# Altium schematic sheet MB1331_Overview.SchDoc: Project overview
size A4; Date: Not used; ApprovedBy: Not used; CheckedBy: Not used; Author: Not used; CompanyName: STMicroelectronics; DrawnBy: Not used; Engineer: Not used; Organization: Not used; Address1: Not used; Address2: Not used; Address3: Not used; Address4: Not used; DocumentNumber: Not used; Revision: Not used; SheetNumber: 1; SheetTotal: 23
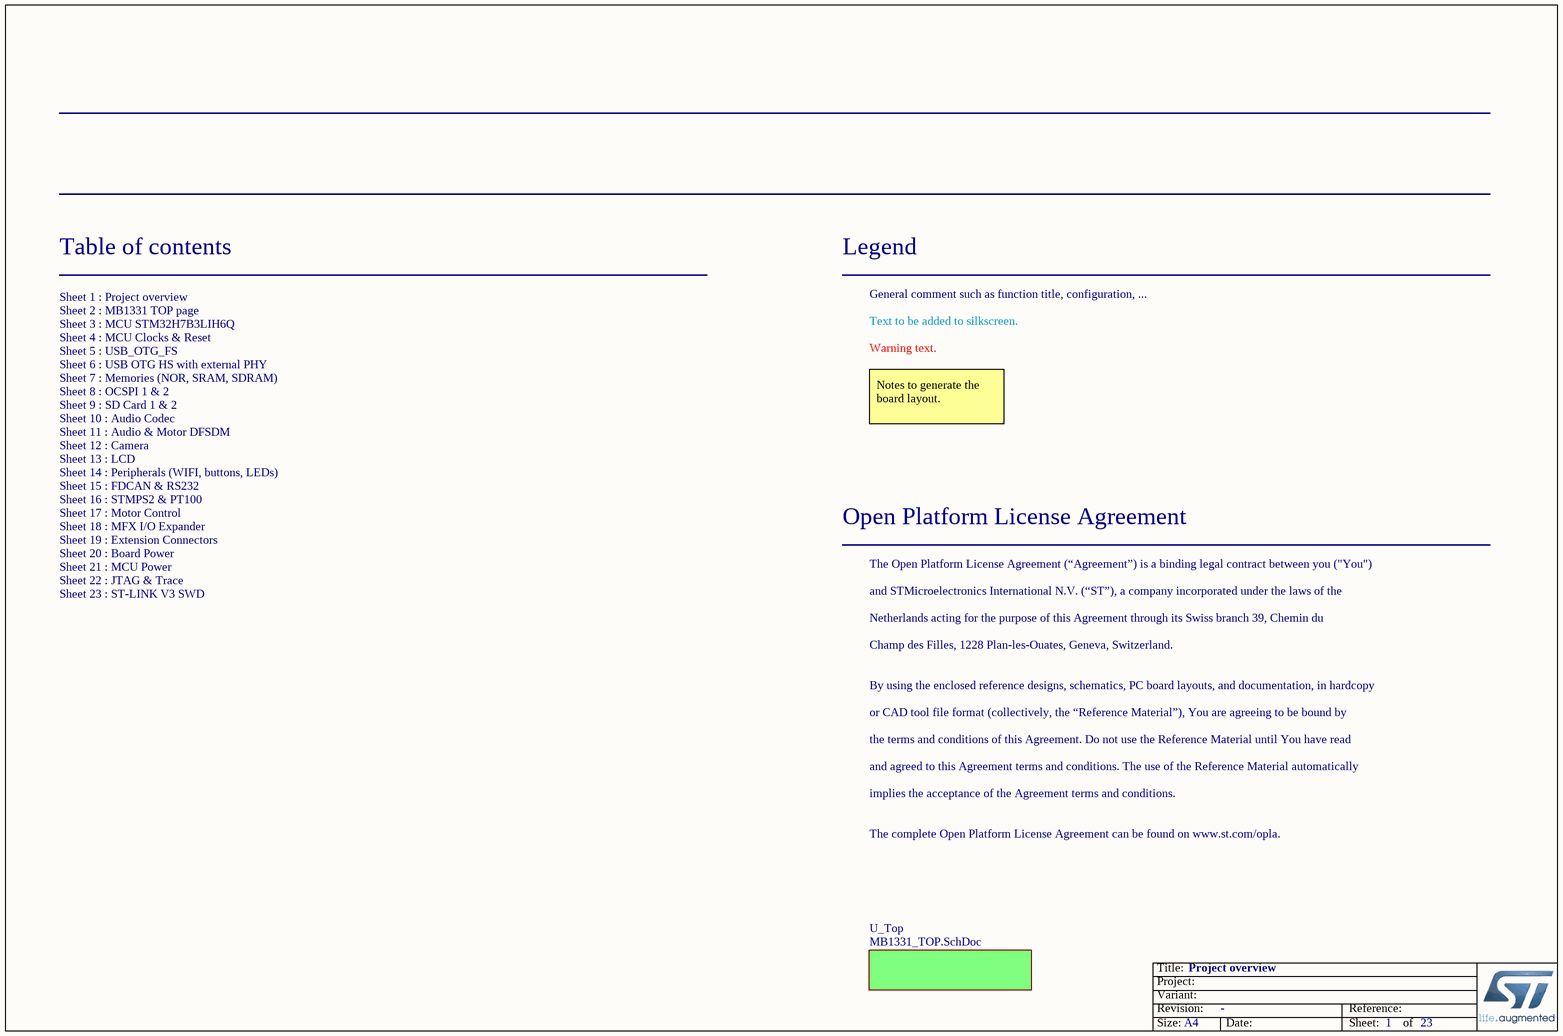
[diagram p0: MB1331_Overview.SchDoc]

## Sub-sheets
U_Top = MB1331_TOP.SchDoc: no entries

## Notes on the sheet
- Table of contents
- Legend
- General comment such as function title, configuration, ...
- Text to be added to silkscreen.
- Warning text.
- Notes to generate the board layout.
- Open Platform License Agreement
- The Open Platform License Agreement (“Agreement”) is a binding legal contract between you ("You")
- Sheet 1 : Project overview
  Sheet 2 : MB1331 TOP page
  Sheet 3 : MCU STM32H7B3LIH6Q
  Sheet 4 : MCU Clocks & Reset
  Sheet 5 : USB_OTG_FS
  Sheet 6 : USB OTG HS with external PHY
  Sheet 7 : Memories (NOR, SRAM, SDRAM)
  Sheet 8 : OCSPI 1 & 2
  Sheet 9 : SD Card 1 & 2
  Sheet 10 : Audio Codec
  Sheet 11 : Audio & Motor DFSDM
  Sheet 12 : Camera
  Sheet 13 : LCD
  Sheet 14 : Peripherals (WIFI, buttons, LEDs)
  Sheet 15 : FDCAN & RS232
  Sheet 16 : STMPS2 & PT100
  Sheet 17 : Motor Control
  Sheet 18 : MFX I/O Expander
  Sheet 19 : Extension Connectors
  Sheet 20 : Board Power
  Sheet 21 : MCU Power
  Sheet 22 : JTAG & Trace
  Sheet 23 : ST-LINK V3 SWD
- and STMicroelectronics International N.V. (“ST”), a company incorporated under the laws of the
- Netherlands acting for the purpose of this Agreement through its Swiss branch 39, Chemin du
- Champ des Filles, 1228 Plan-les-Ouates, Geneva, Switzerland.
- By using the enclosed reference designs, schematics, PC board layouts, and documentation, in hardcopy
- or CAD tool file format (collectively, the “Reference Material”), You are agreeing to be bound by
- the terms and conditions of this Agreement. Do not use the Reference Material until You have read
- and agreed to this Agreement terms and conditions. The use of the Reference Material automatically
- implies the acceptance of the Agreement terms and conditions.
- The complete Open Platform License Agreement can be found on www.st.com/opla.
